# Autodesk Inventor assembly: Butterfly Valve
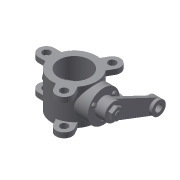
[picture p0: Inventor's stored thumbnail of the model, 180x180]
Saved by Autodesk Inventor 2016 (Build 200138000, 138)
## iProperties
Created: 2011-07
Part Number: Butterfly Valve
Document SubType Name: Assembly
Designer: CadCim
Author: CadCim
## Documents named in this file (8)
- D:\KAVITA\Autodesk Inventor_ 2016 Project_Kavita\Inventor_Part Files\Inventor_2016_tut\c09_Inv_tut_2016\c09_tut01_inv\Butterfly Valve\Butterfly Valve.iam
- D:\KAVITA\Autodesk Inventor_ 2016 Project_Kavita\Inventor_Part Files\Inventor_2016_tut\c09_Inv_tut_2016\c09_tut01_inv\Butterfly Valve\Body.ipt
- D:\KAVITA\Autodesk Inventor_ 2016 Project_Kavita\Inventor_Part Files\Inventor_2016_tut\c09_Inv_tut_2016\c09_tut01_inv\Butterfly Valve\Shaft.ipt
- D:\KAVITA\Autodesk Inventor_ 2016 Project_Kavita\Inventor_Part Files\Inventor_2016_tut\c09_Inv_tut_2016\c09_tut01_inv\Butterfly Valve\Retainer.ipt
- D:\KAVITA\Autodesk Inventor_ 2016 Project_Kavita\Inventor_Part Files\Inventor_2016_tut\c09_Inv_tut_2016\c09_tut01_inv\Butterfly Valve\Arm.ipt
- D:\KAVITA\Autodesk Inventor_ 2016 Project_Kavita\Inventor_Part Files\Inventor_2016_tut\c09_Inv_tut_2016\c09_tut01_inv\Butterfly Valve\Plate.ipt
- D:\KAVITA\Autodesk Inventor_ 2016 Project_Kavita\Inventor_Part Files\Inventor_2016_tut\c09_Inv_tut_2016\c09_tut01_inv\Butterfly Valve\Screw.ipt
- D:\KAVITA\Autodesk Inventor_ 2016 Project_Kavita\Inventor_Part Files\Inventor_2016_tut\c09_Inv_tut_2016\c09_tut01_inv\Butterfly Valve\Nut.ipt
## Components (9 placed, 7 different names)
1. Body:1 — Insert:1, Insert:2, Insert:3, Angle:1
2. Shaft:1 — Insert:1, Mate:1, Angle:1, Insert:5, Insert:6, Insert:10
3. Retainer:1 — Insert:2, Insert:3, Insert:4, Insert:7, Insert:8, Insert:9
4. Arm:1 — Insert:4, Mate:1
5. Plate:1 — Insert:5, Insert:6
6. Screw:1 — Insert:7
7. Screw:2 — Insert:8
8. Screw:3 — Insert:9
9. Nut:1 — Insert:10
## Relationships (12: Insert 10, Mate 1, Angle 1)
- Insert:1: Body:1 ↔ Shaft:1
- Insert:2: Body:1 ↔ Retainer:1
- Insert:3: Body:1 ↔ Retainer:1
- Insert:4: Retainer:1 ↔ Arm:1
- Mate:1: Shaft:1 ↔ Arm:1
- Angle:1: Body:1 ↔ Shaft:1
- Insert:5: Shaft:1 ↔ Plate:1
- Insert:6: Shaft:1 ↔ Plate:1
- Insert:7: Retainer:1 ↔ Screw:1
- Insert:8: Retainer:1 ↔ Screw:2
- Insert:9: Retainer:1 ↔ Screw:3
- Insert:10: Shaft:1 ↔ Nut:1
